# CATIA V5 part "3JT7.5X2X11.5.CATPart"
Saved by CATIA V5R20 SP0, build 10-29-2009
Part number: 3JT7.5X2X11.5
Revision: ANY
Definition: UNKNOWN
Nomenclature: 3JT7.5X2X11.5
Source: Unknown
Bounding box of the stored display mesh (mm): x -5.75 to 5.75, y -5.75 to 5.75, z -1 to 1
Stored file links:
  C:\Users\Utente\Desktop\IO LAVORO\3D X SITO CF\CUMSA\3D files PW\pw060630\pw060630_ejection\3JT7.5X2X11.5.CATPart
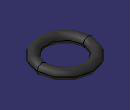
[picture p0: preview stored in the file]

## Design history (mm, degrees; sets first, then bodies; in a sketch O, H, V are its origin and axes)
Body1 "Revolución1" (main body)
  Solid1: solid without history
